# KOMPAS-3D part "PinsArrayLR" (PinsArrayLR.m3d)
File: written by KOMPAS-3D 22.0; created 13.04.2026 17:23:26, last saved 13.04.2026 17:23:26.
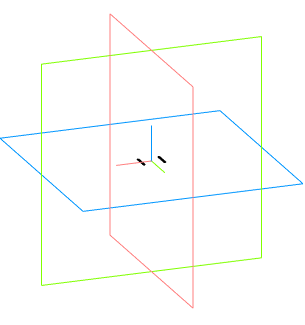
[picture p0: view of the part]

Document properties: Автор: Andrey; Полное имя файла: C:\Users\User1\Documents\PinsArrayLR.m3d

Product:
- Part/product: PinsArrayLR

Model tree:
1. Операция без истории:1
2. Операция без истории:2
3. Операция без истории:3
4. Операция без истории:4
5. Операция без истории:5
6. Операция без истории:6
7. Операция без истории:7
8. Операция без истории:8
9. Операция без истории:9
10. Операция без истории:10
11. Операция без истории:11
12. Операция без истории:12
13. Операция без истории:13
14. Операция без истории:14
15. Операция без истории:15
16. Операция без истории:16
